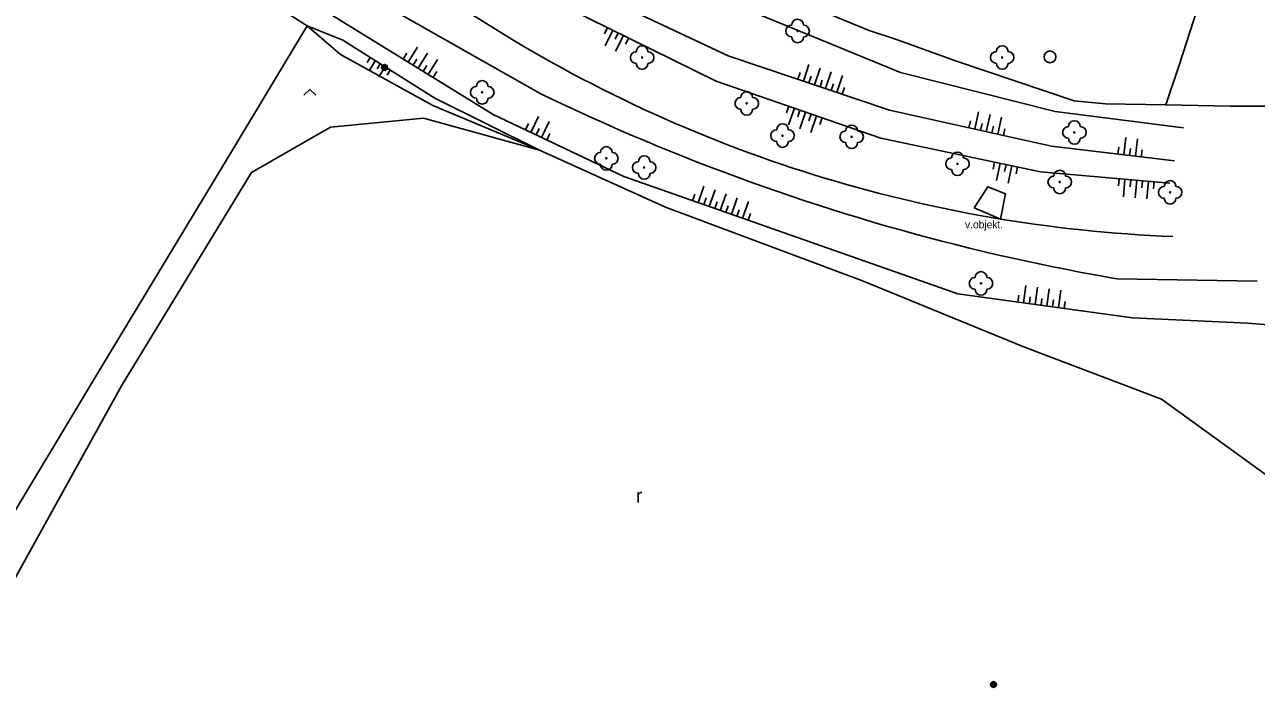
# Model space of a CAD drawing. Extents: x -539515 to -538098, y -1182060 to -1180157.
# Drawn here: x -538510.9 to -538406.1, y -1181824.6 to -1181768.2 of the extents above; entities that cross this region are included whole.
import ezdxf

# ---------------------------------------------------------------- set-up
doc = ezdxf.new("R2010")
doc.units = 0
for name, color, linetype in [('Vrstva 13', 7, 'Continuous'), ('Vrstva 21', 7, 'Continuous'), ('Vrstva 22', 7, 'Continuous'), ('Vrstva 23', 7, 'Continuous'), ('Vrstva 25', 7, 'Continuous'), ('Vrstva 27', 7, 'Continuous'), ('Vrstva 29', 7, 'Continuous'), ('Vrstva 36', 7, 'Continuous'), ('Vrstva 40', 7, 'Continuous'), ('Vrstva 68', 7, 'Continuous')]:
    doc.layers.add(name, color=color, linetype=linetype)

msp = doc.modelspace()

# ---------------------------------------------------------------- linework, layer by layer
at = {"layer": 'Vrstva 13'}
msp.add_lwpolyline([(-538430.11, -1181783.8), (-538428.95, -1181782.01), (-538427.45, -1181782.6), (-538427.88, -1181784.77), (-538429.18, -1181784.19), (-538430.11, -1181783.8)], dxfattribs=at)
at = {"layer": 'Vrstva 21'}
for p, q in [((-538410.81, -1181765.85), (-538412.72, -1181771.75)), ((-538412.72, -1181771.75), (-538413.8, -1181775.02))]:
    msp.add_line(p, q, dxfattribs=at)
at = {"layer": 'Vrstva 22'}
for centre in [(-538445.14, -1181768.75), (-538458.37, -1181771.01), (-538427.73, -1181771), (-538471.97, -1181773.97), (-538449.47, -1181774.91), (-538421.59, -1181777.38), (-538446.42, -1181777.65), (-538440.54, -1181777.75), (-538461.41, -1181779.59), (-538458.19, -1181780.37), (-538431.54, -1181780.05), (-538422.84, -1181781.6), (-538413.45, -1181782.48), (-538429.54, -1181790.23)]:
    msp.add_circle(centre, 0.05, dxfattribs=at)
for centre, start, end in [((-538445.14, -1181768.25), 0, 180), ((-538445.64, -1181768.75), 90, 270), ((-538444.64, -1181768.75), 270, 90), ((-538458.37, -1181770.51), 0, 180), ((-538445.14, -1181769.25), 180, 0), ((-538427.73, -1181770.5), 0, 180), ((-538458.87, -1181771.01), 90, 270), ((-538457.87, -1181771.01), 270, 90), ((-538428.23, -1181771), 90, 270), ((-538427.23, -1181771), 270, 90), ((-538458.37, -1181771.51), 180, 0), ((-538427.73, -1181771.5), 180, 0), ((-538471.97, -1181773.47), 0, 180), ((-538472.47, -1181773.97), 90, 270), ((-538471.47, -1181773.97), 270, 90), ((-538449.97, -1181774.91), 90, 270), ((-538449.47, -1181774.41), 0, 180), ((-538448.97, -1181774.91), 270, 90), ((-538471.97, -1181774.47), 180, 0), ((-538449.47, -1181775.41), 180, 0), ((-538421.59, -1181776.88), 0, 180), ((-538446.92, -1181777.65), 90, 270), ((-538446.42, -1181777.15), 0, 180), ((-538445.92, -1181777.65), 270, 90), ((-538441.04, -1181777.75), 90, 270), ((-538440.54, -1181777.25), 0, 180), ((-538440.04, -1181777.75), 270, 90), ((-538422.09, -1181777.38), 90, 270), ((-538421.09, -1181777.38), 270, 90), ((-538461.41, -1181779.09), 0, 180), ((-538446.42, -1181778.15), 180, 0), ((-538440.54, -1181778.25), 180, 0), ((-538421.59, -1181777.88), 180, 0), ((-538461.91, -1181779.59), 90, 270), ((-538460.91, -1181779.59), 270, 90), ((-538458.19, -1181779.87), 0, 180), ((-538432.04, -1181780.05), 90, 270), ((-538431.54, -1181779.55), 0, 180), ((-538431.04, -1181780.05), 270, 90), ((-538461.41, -1181780.09), 180, 0), ((-538458.69, -1181780.37), 90, 270), ((-538457.69, -1181780.37), 270, 90), ((-538431.54, -1181780.55), 180, 0), ((-538422.84, -1181781.1), 0, 180), ((-538458.19, -1181780.87), 180, 0), ((-538423.34, -1181781.6), 90, 270), ((-538422.34, -1181781.6), 270, 90), ((-538413.45, -1181781.98), 0, 180), ((-538422.84, -1181782.1), 180, 0), ((-538413.95, -1181782.48), 90, 270), ((-538412.95, -1181782.48), 270, 90), ((-538413.45, -1181782.98), 180, 0), ((-538430.04, -1181790.23), 90, 270), ((-538429.54, -1181789.73), 0, 180), ((-538429.04, -1181790.23), 270, 90), ((-538429.54, -1181790.73), 180, 0)]:
    msp.add_arc(centre, 0.5, start, end, dxfattribs=at)
at = {"layer": 'Vrstva 23'}
for p, q in [((-538484.89, -1181776.94), (-538476.97, -1181776.16)), ((-538476.97, -1181776.16), (-538467.09, -1181778.9)), ((-538491.61, -1181780.79), (-538484.89, -1181776.94)), ((-538467.09, -1181778.9), (-538456.37, -1181783.73)), ((-538502.65, -1181798.94), (-538491.61, -1181780.79)), ((-538456.37, -1181783.73), (-538439.62, -1181790)), ((-538439.62, -1181790), (-538425.98, -1181795.59)), ((-538425.98, -1181795.59), (-538414.19, -1181800.08)), ((-538514.42, -1181820.18), (-538502.65, -1181798.94)), ((-538414.19, -1181800.08), (-538402.44, -1181808.58))]:
    msp.add_line(p, q, dxfattribs=at)
at = {"layer": 'Vrstva 25'}
for centre, radius in [((-538480.286, -1181771.846), 0.25), ((-538480.286, -1181771.846), 0.2), ((-538480.286, -1181771.846), 0.15), ((-538480.286, -1181771.846), 0.1), ((-538480.286, -1181771.846), 0.05), ((-538428.468, -1181824.366), 0.25), ((-538428.468, -1181824.366), 0.2), ((-538428.468, -1181824.366), 0.15), ((-538428.468, -1181824.366), 0.1), ((-538428.468, -1181824.366), 0.05)]:
    msp.add_circle(centre, radius, dxfattribs=at)
at = {"layer": 'Vrstva 27'}
for p, q in [((-538461.304, -1181768.456), (-538461.569, -1181768.994)), ((-538460.856, -1181768.677), (-538461.519, -1181770.022)), ((-538460.407, -1181768.898), (-538460.673, -1181769.436)), ((-538459.959, -1181769.119), (-538460.622, -1181770.465)), ((-538478.264, -1181771.399), (-538477.476, -1181770.123)), ((-538459.51, -1181769.34), (-538459.776, -1181769.879)), ((-538481.492, -1181771.012), (-538481.759, -1181771.435)), ((-538481.069, -1181771.279), (-538481.602, -1181772.125)), ((-538478.689, -1181771.136), (-538478.374, -1181770.626)), ((-538477.838, -1181771.662), (-538477.523, -1181771.151)), ((-538477.413, -1181771.925), (-538476.625, -1181770.648)), ((-538476.562, -1181772.45), (-538475.774, -1181771.174)), ((-538480.646, -1181771.545), (-538480.912, -1181771.968)), ((-538480.223, -1181771.811), (-538480.756, -1181772.658)), ((-538479.8, -1181772.078), (-538480.066, -1181772.501)), ((-538476.988, -1181772.187), (-538476.672, -1181771.677)), ((-538476.137, -1181772.713), (-538475.821, -1181772.202)), ((-538445.126, -1181772.851), (-538444.934, -1181772.283)), ((-538444.652, -1181773.011), (-538444.173, -1181771.59)), ((-538443.704, -1181773.33), (-538443.225, -1181771.909)), ((-538442.757, -1181773.65), (-538442.277, -1181772.229)), ((-538444.178, -1181773.171), (-538443.986, -1181772.602)), ((-538443.231, -1181773.49), (-538443.039, -1181772.922)), ((-538442.283, -1181773.81), (-538442.091, -1181773.241)), ((-538441.809, -1181773.97), (-538441.33, -1181772.548)), ((-538441.335, -1181774.129), (-538441.144, -1181773.561)), ((-538445.882, -1181775.158), (-538446.079, -1181775.725)), ((-538445.41, -1181775.322), (-538445.902, -1181776.739)), ((-538444.938, -1181775.486), (-538445.134, -1181776.053)), ((-538467.832, -1181777.383), (-538467.189, -1181776.028)), ((-538466.929, -1181777.812), (-538466.286, -1181776.457)), ((-538444.465, -1181775.65), (-538444.957, -1181777.067)), ((-538443.993, -1181775.814), (-538444.19, -1181776.381)), ((-538443.52, -1181775.978), (-538444.012, -1181777.395)), ((-538443.048, -1181776.142), (-538443.245, -1181776.709)), ((-538430.559, -1181776.992), (-538430.428, -1181776.407)), ((-538430.071, -1181777.101), (-538429.744, -1181775.637)), ((-538429.095, -1181777.319), (-538428.768, -1181775.855)), ((-538428.119, -1181777.537), (-538427.792, -1181776.073)), ((-538468.284, -1181777.169), (-538468.027, -1181776.627)), ((-538467.381, -1181777.598), (-538467.123, -1181777.056)), ((-538466.477, -1181778.026), (-538466.22, -1181777.484)), ((-538429.583, -1181777.21), (-538429.452, -1181776.625)), ((-538428.607, -1181777.428), (-538428.476, -1181776.843)), ((-538427.631, -1181777.646), (-538427.5, -1181777.061)), ((-538417.399, -1181779.294), (-538417.221, -1181777.804)), ((-538416.406, -1181779.412), (-538416.228, -1181777.923)), ((-538417.896, -1181779.235), (-538417.825, -1181778.639)), ((-538416.903, -1181779.353), (-538416.832, -1181778.757)), ((-538415.91, -1181779.472), (-538415.839, -1181778.876)), ((-538428.386, -1181779.915), (-538428.51, -1181780.502)), ((-538427.897, -1181780.018), (-538428.207, -1181781.486)), ((-538427.407, -1181780.122), (-538427.531, -1181780.709)), ((-538426.918, -1181780.225), (-538427.228, -1181781.693)), ((-538426.429, -1181780.328), (-538426.553, -1181780.915)), ((-538417.785, -1181781.318), (-538417.837, -1181781.916)), ((-538417.287, -1181781.361), (-538417.416, -1181782.856)), ((-538416.789, -1181781.404), (-538416.84, -1181782.002)), ((-538416.291, -1181781.447), (-538416.42, -1181782.942)), ((-538415.792, -1181781.49), (-538415.844, -1181782.088)), ((-538415.294, -1181781.533), (-538415.423, -1181783.028)), ((-538414.796, -1181781.576), (-538414.848, -1181782.174)), ((-538454.075, -1181783.196), (-538453.876, -1181782.63)), ((-538453.603, -1181783.362), (-538453.106, -1181781.947)), ((-538452.66, -1181783.694), (-538452.162, -1181782.279)), ((-538451.717, -1181784.026), (-538451.219, -1181782.611)), ((-538453.132, -1181783.528), (-538452.933, -1181782.962)), ((-538452.188, -1181783.86), (-538451.989, -1181783.294)), ((-538451.245, -1181784.192), (-538451.046, -1181783.626)), ((-538450.773, -1181784.357), (-538450.276, -1181782.942)), ((-538449.83, -1181784.689), (-538449.332, -1181783.274)), ((-538450.302, -1181784.523), (-538450.103, -1181783.957)), ((-538449.358, -1181784.855), (-538449.159, -1181784.289)), ((-538425.918, -1181791.898), (-538425.715, -1181790.412)), ((-538424.928, -1181792.034), (-538424.724, -1181790.548)), ((-538423.937, -1181792.17), (-538423.733, -1181790.684)), ((-538422.946, -1181792.305), (-538422.742, -1181790.819)), ((-538426.414, -1181791.83), (-538426.332, -1181791.236)), ((-538425.423, -1181791.966), (-538425.342, -1181791.371)), ((-538424.432, -1181792.102), (-538424.351, -1181791.507)), ((-538423.442, -1181792.238), (-538423.36, -1181791.643)), ((-538422.451, -1181792.373), (-538422.369, -1181791.779))]:
    msp.add_line(p, q, dxfattribs=at)
msp.add_circle((-538423.67, -1181770.95), 0.5, dxfattribs=at)
at = {"layer": 'Vrstva 29'}
for p, q in [((-538491.43, -1181760.23), (-538467.03, -1181774.07)), ((-538493.42, -1181762.04), (-538471.04, -1181775.86)), ((-538451.06, -1181770.85), (-538469.21, -1181762.31)), ((-538452.07, -1181773.01), (-538470.46, -1181763.94)), ((-538436.38, -1181772.28), (-538449.95, -1181766.71)), ((-538486.86, -1181768.3), (-538484.02, -1181770.76)), ((-538486.86, -1181768.3), (-538483.83, -1181769.54)), ((-538483.83, -1181769.54), (-538476, -1181774.47)), ((-538484.02, -1181770.76), (-538476.17, -1181775.1)), ((-538437.33, -1181775.48), (-538451.06, -1181770.85)), ((-538423.23, -1181775.6), (-538436.38, -1181772.28)), ((-538438.07, -1181777.87), (-538452.07, -1181773.01)), ((-538476.17, -1181775.1), (-538467.09, -1181778.9)), ((-538476, -1181774.47), (-538467.09, -1181778.9)), ((-538423.54, -1181778.56), (-538437.33, -1181775.48)), ((-538471.04, -1181775.86), (-538459.92, -1181781.14)), ((-538412.3, -1181776.99), (-538423.23, -1181775.6)), ((-538455.607, -1181776.583), (-538454.713, -1181776.966)), ((-538424.48, -1181780.74), (-538438.07, -1181777.87)), ((-538413.08, -1181779.81), (-538423.54, -1181778.56)), ((-538445.621, -1181780.386), (-538444.697, -1181780.687)), ((-538459.92, -1181781.14), (-538431.52, -1181791.13)), ((-538449.122, -1181781.61), (-538447.977, -1181782.018)), ((-538413.48, -1181781.69), (-538424.48, -1181780.74)), ((-538435.333, -1181783.271), (-538434.386, -1181783.487)), ((-538438.73, -1181785.01), (-538437.564, -1181785.35)), ((-538424.826, -1181785.214), (-538423.863, -1181785.343)), ((-538428.156, -1181787.789), (-538426.971, -1181788.059)), ((-538417.94, -1181789.85), (-538406.04, -1181790.05)), ((-538431.52, -1181791.13), (-538416.64, -1181793.17)), ((-538416.64, -1181793.17), (-538406.85, -1181793.61)), ((-538406.85, -1181793.61), (-538384.94, -1181795.39))]:
    msp.add_line(p, q, dxfattribs=at)
for points in [[(-538472.72, -1181767.42), (-538471.902, -1181767.944), (-538471.079, -1181768.462), (-538470.253, -1181768.972), (-538469.422, -1181769.476), (-538468.587, -1181769.973), (-538467.748, -1181770.463), (-538466.905, -1181770.946), (-538466.058, -1181771.422), (-538465.207, -1181771.892), (-538464.352, -1181772.354)], [(-538464.352, -1181772.354), (-538463.493, -1181772.809), (-538462.631, -1181773.257), (-538461.765, -1181773.698), (-538460.896, -1181774.132), (-538460.023, -1181774.558), (-538459.146, -1181774.978), (-538458.266, -1181775.39), (-538457.383, -1181775.795), (-538456.496, -1181776.192), (-538455.607, -1181776.583)], [(-538467.03, -1181774.07), (-538465.935, -1181774.596), (-538464.836, -1181775.115), (-538463.734, -1181775.627), (-538462.629, -1181776.131), (-538461.52, -1181776.628), (-538460.408, -1181777.118), (-538459.293, -1181777.601), (-538458.175, -1181778.076)], [(-538454.713, -1181776.966), (-538453.817, -1181777.341), (-538452.918, -1181777.709), (-538452.016, -1181778.07), (-538451.111, -1181778.424), (-538450.203, -1181778.769), (-538449.292, -1181779.108), (-538448.378, -1181779.439), (-538447.462, -1181779.762), (-538446.543, -1181780.078), (-538445.621, -1181780.386)], [(-538458.175, -1181778.076), (-538457.054, -1181778.544), (-538455.929, -1181779.004), (-538454.802, -1181779.457), (-538453.672, -1181779.903), (-538452.538, -1181780.341), (-538451.402, -1181780.772), (-538450.263, -1181781.195), (-538449.122, -1181781.61)], [(-538444.697, -1181780.687), (-538443.771, -1181780.98), (-538442.842, -1181781.265), (-538441.911, -1181781.543), (-538440.978, -1181781.813), (-538440.042, -1181782.075), (-538439.104, -1181782.33), (-538438.164, -1181782.577), (-538437.223, -1181782.816), (-538436.279, -1181783.047), (-538435.333, -1181783.271)], [(-538447.977, -1181782.018), (-538446.83, -1181782.419), (-538445.68, -1181782.812), (-538444.528, -1181783.197), (-538443.373, -1181783.575), (-538442.216, -1181783.945), (-538441.057, -1181784.308), (-538439.895, -1181784.663), (-538438.73, -1181785.01)], [(-538434.386, -1181783.487), (-538433.437, -1181783.695), (-538432.486, -1181783.895), (-538431.533, -1181784.087), (-538430.579, -1181784.272), (-538429.624, -1181784.449), (-538428.667, -1181784.617), (-538427.88, -1181784.77), (-538426.749, -1181784.931), (-538425.788, -1181785.077), (-538424.826, -1181785.214)], [(-538437.564, -1181785.35), (-538436.395, -1181785.682), (-538435.224, -1181786.006), (-538434.051, -1181786.323), (-538432.876, -1181786.631), (-538431.699, -1181786.932), (-538430.52, -1181787.226), (-538429.339, -1181787.511), (-538428.156, -1181787.789)], [(-538423.863, -1181785.343), (-538422.899, -1181785.464), (-538421.934, -1181785.578), (-538420.968, -1181785.683), (-538420.001, -1181785.781), (-538419.034, -1181785.87), (-538418.066, -1181785.952), (-538417.097, -1181786.025), (-538416.127, -1181786.091), (-538415.157, -1181786.148)], [(-538415.157, -1181786.148), (-538414.187, -1181786.198), (-538413.21, -1181786.24)], [(-538426.971, -1181788.059), (-538425.785, -1181788.321), (-538424.597, -1181788.575), (-538423.407, -1181788.822), (-538422.216, -1181789.06), (-538421.023, -1181789.291), (-538419.828, -1181789.514), (-538418.633, -1181789.729), (-538417.94, -1181789.85)]]:
    msp.add_lwpolyline(points, dxfattribs=at)
at = {"layer": 'Vrstva 36'}
msp.add_lwpolyline([(-538487.138, -1181774.221), (-538486.638, -1181773.721), (-538486.138, -1181774.221)], dxfattribs=at)
at = {"layer": 'Vrstva 68'}
for p, q in [((-538486.86, -1181768.3), (-538526.69, -1181743.11)), ((-538486.86, -1181768.3), (-538493.18, -1181778.82)), ((-538436.72, -1181769.46), (-538439.14, -1181768.67)), ((-538418.95, -1181774.96), (-538421.6, -1181774.7)), ((-538413.8, -1181775.02), (-538418.95, -1181774.96)), ((-538408.35, -1181775.15), (-538413.8, -1181775.02)), ((-538392.45, -1181775.17), (-538408.35, -1181775.15)), ((-538493.18, -1181778.82), (-538504.61, -1181797.75)), ((-538504.61, -1181797.75), (-538515.66, -1181816.11))]:
    msp.add_line(p, q, dxfattribs=at)
for points in [[(-538439.14, -1181768.67), (-538441.76, -1181767.6), (-538448.94, -1181764.43)], [(-538421.6, -1181774.7), (-538431.72, -1181771.28), (-538436.72, -1181769.46)]]:
    msp.add_lwpolyline(points, dxfattribs=at)

# ---------------------------------------------------------------- texts
at = {"layer": 'Vrstva 36'}
msp.add_text('r', height=1.2, dxfattribs=at).set_placement((-538458.892, -1181808.884))
at = {"layer": 'Vrstva 40'}
msp.add_text('v.objekt.', height=0.65, dxfattribs=at).set_placement((-538430.896, -1181785.542))

doc.saveas('drawing.dxf')
